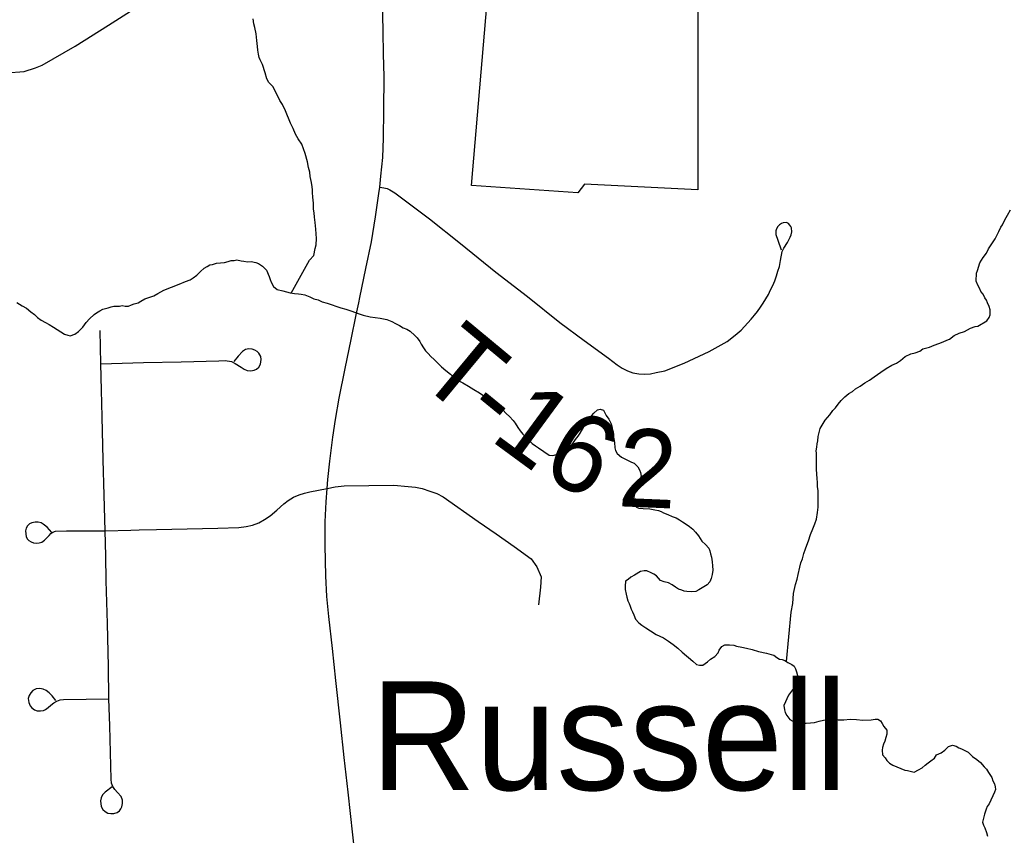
# Model space of a CAD drawing. Extents: x -11.4 to 84.1, y 11.1 to 59.
# Drawn here: x 28.225 to 28.944, y 44.128 to 44.72 of the extents above; entities that cross this region are included whole.
import ezdxf

# ---------------------------------------------------------------- set-up
doc = ezdxf.new("R2010")
doc.units = 0
for name, color, linetype in [('GM_X_Corporation', 7, 'Continuous'), ('GM_X_Minor_River', 7, 'Continuous'), ('GM_X_State_Route', 7, 'Continuous'), ('GM_X_Township_Road', 7, 'Continuous'), ('GM_X_Township_Road_Text', 7, 'Continuous'), ('GM_X_Unincorporated_Text', 7, 'Continuous')]:
    doc.layers.add(name, color=color, linetype=linetype)

msp = doc.modelspace()

# ---------------------------------------------------------------- linework, layer by layer
at = {"layer": 'GM_X_Corporation'}
msp.add_lwpolyline([(28.7167, 44.89422), (28.71711, 44.59705), (28.63473, 44.60119), (28.6298, 44.59474), (28.55271, 44.60006), (28.59239, 45.06585)], dxfattribs=at)
at = {"layer": 'GM_X_Minor_River'}
for points in [[(28.42157, 44.52201), (28.43502, 44.54588), (28.438, 44.54935), (28.43906, 44.55431), (28.43977, 44.55699), (28.44008, 44.56156), (28.43958, 44.56839), (28.43912, 44.57333), (28.43868, 44.57712), (28.43825, 44.58016), (28.43782, 44.58281), (28.43779, 44.58471), (28.43775, 44.58738), (28.43729, 44.59155), (28.43724, 44.59497), (28.43721, 44.59687), (28.43679, 44.59915), (28.43636, 44.60218), (28.43594, 44.60446), (28.43552, 44.60673), (28.43509, 44.60977), (28.43427, 44.61318), (28.43344, 44.61734), (28.43183, 44.6234), (28.42943, 44.63021), (28.42671, 44.63396), (28.42475, 44.63736), (28.42316, 44.64151), (28.4212, 44.64528), (28.41763, 44.65435), (28.41528, 44.65888), (28.41333, 44.66188), (28.41135, 44.66642), (28.40822, 44.67207), (28.40551, 44.67506), (28.40394, 44.6777), (28.40274, 44.68186), (28.40074, 44.68792), (28.39916, 44.69131), (28.39837, 44.6932), (28.39795, 44.69547), (28.39752, 44.69851), (28.39709, 44.70116), (28.39665, 44.70534), (28.39618, 44.71028), (28.39535, 44.71482), (28.39454, 44.71747), (28.3941, 44.72127)], [(28.94192, 44.57856), (28.94413, 44.58239)], [(28.78144, 44.25418), (28.78495, 44.29002), (28.78598, 44.2965), (28.78662, 44.30374), (28.78803, 44.31023), (28.78911, 44.31405), (28.78981, 44.31748), (28.79124, 44.32283), (28.79195, 44.32588), (28.79304, 44.32894), (28.79411, 44.33276), (28.79519, 44.3362), (28.79629, 44.33888), (28.79738, 44.34194), (28.79882, 44.34653), (28.80065, 44.35074), (28.80211, 44.35419), (28.80319, 44.35763), (28.80386, 44.36258), (28.80456, 44.3664), (28.80451, 44.36944), (28.80446, 44.37248), (28.8044, 44.3759), (28.80436, 44.37856), (28.80393, 44.38121), (28.80388, 44.38426), (28.80383, 44.3873), (28.80334, 44.39375), (28.80326, 44.3987), (28.8032, 44.4025), (28.80315, 44.40554), (28.80311, 44.40744), (28.80345, 44.41011), (28.80379, 44.41239), (28.80413, 44.41468), (28.80446, 44.41773), (28.80588, 44.42345), (28.80958, 44.4296), (28.81293, 44.43346), (28.81516, 44.43654), (28.81703, 44.43847), (28.81888, 44.44116), (28.82111, 44.44386), (28.82373, 44.44656), (28.82673, 44.4489), (28.82936, 44.45046), (28.83161, 44.4524), (28.83499, 44.45435), (28.83837, 44.45669), (28.84176, 44.45865), (28.84514, 44.46099), (28.85001, 44.46449), (28.85377, 44.46721), (28.8579, 44.46956), (28.8613, 44.47114), (28.8643, 44.47309), (28.86768, 44.47581), (28.87182, 44.47778), (28.87485, 44.47859), (28.87824, 44.47978), (28.8805, 44.48134), (28.88541, 44.48256), (28.8888, 44.48414), (28.8922, 44.48534), (28.89522, 44.48652), (28.89786, 44.48771), (28.89975, 44.4885), (28.90312, 44.49122), (28.90689, 44.4928), (28.91067, 44.494), (28.91293, 44.49518), (28.91519, 44.49636), (28.91859, 44.49756), (28.92048, 44.49797), (28.92687, 44.50188), (28.92873, 44.50419), (28.92946, 44.5061), (28.92939, 44.5099), (28.9286, 44.51217), (28.92741, 44.51481), (28.92662, 44.5167), (28.92545, 44.51858), (28.92427, 44.52123), (28.92272, 44.5231), (28.92193, 44.52499), (28.92036, 44.52763), (28.91917, 44.53065), (28.91946, 44.53636), (28.92018, 44.53827), (28.92198, 44.54401), (28.9242, 44.54784), (28.92681, 44.55093), (28.92827, 44.55399), (28.93049, 44.55783), (28.93309, 44.5613), (28.93456, 44.56437), (28.93566, 44.56667), (28.93713, 44.56973), (28.93823, 44.57165), (28.94008, 44.5751), (28.94192, 44.57856)], [(28.35316, 44.53503), (28.35578, 44.53774), (28.3584, 44.54006), (28.36065, 44.54124), (28.36253, 44.54241), (28.36443, 44.54282), (28.36745, 44.54363), (28.37314, 44.5441), (28.37579, 44.54491), (28.37805, 44.54571), (28.38033, 44.54574), (28.38222, 44.54616), (28.38527, 44.54545), (28.38718, 44.54509), (28.38984, 44.54476), (28.3925, 44.5448), (28.39593, 44.5441), (28.39784, 44.54337), (28.40091, 44.54152), (28.40362, 44.53852), (28.4056, 44.53399), (28.40639, 44.53172), (28.40718, 44.52983), (28.40875, 44.52682), (28.41145, 44.52458), (28.41565, 44.52351), (28.41832, 44.52279), (28.42099, 44.52208), (28.42403, 44.52175), (28.42708, 44.52142), (28.42898, 44.52107), (28.43165, 44.52073), (28.43509, 44.51927), (28.43815, 44.5178), (28.4412, 44.51709), (28.44427, 44.51561), (28.4477, 44.51453), (28.45763, 44.51127), (28.46145, 44.51019), (28.46565, 44.50874), (28.46948, 44.50728), (28.47406, 44.50584), (28.47901, 44.50478), (28.48625, 44.50376), (28.4912, 44.5027), (28.49465, 44.50123), (28.49733, 44.49976), (28.50039, 44.49829), (28.50308, 44.49681), (28.50575, 44.49571), (28.50806, 44.49423), (28.51152, 44.49124), (28.51308, 44.48937), (28.51502, 44.48674), (28.51619, 44.48485), (28.51775, 44.48222), (28.51931, 44.47996), (28.52124, 44.47809), (28.52318, 44.47584), (28.52549, 44.4736), (28.5282, 44.47098), (28.5309, 44.46837), (28.53398, 44.46576), (28.53744, 44.46315), (28.54093, 44.45941), (28.54629, 44.45683), (28.55051, 44.45424), (28.55434, 44.45202), (28.55856, 44.44943), (28.5624, 44.44683), (28.56625, 44.44423), (28.56971, 44.44163), (28.57279, 44.4394), (28.57548, 44.43716), (28.5778, 44.43453), (28.58012, 44.43229), (28.58283, 44.42929), (28.58438, 44.42742), (28.58633, 44.42441), (28.58789, 44.42177), (28.58983, 44.41952), (28.59215, 44.41728), (28.59447, 44.41503), (28.59678, 44.41279), (28.59909, 44.41093), (28.6014, 44.40945), (28.60908, 44.40425), (28.61174, 44.40391), (28.61439, 44.40471), (28.61778, 44.40629), (28.62079, 44.40786), (28.62342, 44.40981), (28.62529, 44.41136), (28.62678, 44.41328), (28.62826, 44.41559), (28.63012, 44.4179), (28.6316, 44.42021), (28.63418, 44.42481), (28.63714, 44.42981), (28.63974, 44.43289), (28.64161, 44.43482)], [(28.22246, 44.51501), (28.22629, 44.51279), (28.22936, 44.51094), (28.23245, 44.50833), (28.23514, 44.50647), (28.23745, 44.50423), (28.24014, 44.50237), (28.24321, 44.50052), (28.2459, 44.49904), (28.24897, 44.49719), (28.25703, 44.492), (28.25932, 44.49128), (28.26122, 44.49093), (28.26462, 44.49213), (28.26725, 44.49407), (28.27024, 44.49716), (28.27284, 44.50063), (28.27507, 44.50332), (28.27844, 44.50642), (28.28032, 44.50759), (28.28257, 44.50915), (28.28483, 44.51033), (28.28861, 44.51115), (28.29088, 44.51195), (28.29277, 44.51236), (28.29467, 44.51239), (28.29695, 44.51243), (28.29884, 44.51284), (28.30112, 44.5125), (28.3034, 44.51254), (28.30567, 44.51334), (28.30755, 44.51413), (28.31058, 44.51494), (28.31246, 44.51611), (28.31547, 44.51768), (28.31887, 44.51888), (28.32189, 44.52007), (28.3249, 44.52164), (28.32904, 44.52399), (28.3347, 44.52636), (28.34036, 44.52836), (28.34488, 44.53033), (28.34828, 44.53153), (28.35054, 44.53309), (28.35316, 44.53503)], [(28.64161, 44.43482), (28.64423, 44.43715), (28.64612, 44.43756), (28.64841, 44.43684), (28.65038, 44.43306), (28.65232, 44.43044), (28.65389, 44.42742), (28.65469, 44.42515), (28.65512, 44.42212), (28.65555, 44.4187), (28.65598, 44.41605), (28.6564, 44.41339), (28.65685, 44.4096), (28.65726, 44.4077), (28.65843, 44.40544), (28.66152, 44.40283), (28.66458, 44.40136), (28.6665, 44.40025), (28.6688, 44.39915), (28.67071, 44.39842), (28.67341, 44.3958), (28.67459, 44.39354), (28.67538, 44.39165), (28.6758, 44.38899), (28.67403, 44.38174), (28.67255, 44.37906), (28.67108, 44.37599), (28.67038, 44.37255), (28.67083, 44.36876), (28.67238, 44.3665), (28.67429, 44.36577), (28.67734, 44.36544), (28.68228, 44.36514), (28.68571, 44.36444), (28.68837, 44.3641), (28.69029, 44.36338), (28.6922, 44.36227), (28.69526, 44.36117), (28.69832, 44.3597), (28.70138, 44.35861), (28.70368, 44.35713), (28.70599, 44.35565), (28.70791, 44.35454), (28.71098, 44.35231), (28.71329, 44.35045), (28.71523, 44.34819), (28.71755, 44.34557), (28.7199, 44.34181), (28.7226, 44.33919), (28.72492, 44.33657), (28.72571, 44.33468), (28.72613, 44.3324), (28.72693, 44.33014), (28.72736, 44.32672), (28.72779, 44.32368), (28.72785, 44.32064), (28.72752, 44.3176), (28.72681, 44.31454), (28.72571, 44.31224), (28.72385, 44.30993), (28.71783, 44.30641), (28.71557, 44.30523), (28.71216, 44.30479), (28.70911, 44.30513), (28.70721, 44.30548), (28.7053, 44.3062), (28.70301, 44.30693), (28.7007, 44.30841), (28.6984, 44.30989), (28.69572, 44.31137), (28.69267, 44.31208), (28.68999, 44.31318), (28.6869, 44.31655), (28.68497, 44.31766), (28.68306, 44.31877), (28.67999, 44.32024), (28.6781, 44.32021), (28.67544, 44.31978), (28.67093, 44.31705), (28.6683, 44.31548), (28.66643, 44.31393), (28.66455, 44.31276), (28.66423, 44.30895), (28.66427, 44.30667), (28.66509, 44.30326), (28.6655, 44.30099), (28.66631, 44.29834), (28.6671, 44.29645), (28.66789, 44.29456), (28.66869, 44.29229), (28.66948, 44.29041), (28.67066, 44.28814), (28.67185, 44.28512), (28.67417, 44.2825), (28.67648, 44.28063), (28.67917, 44.27877), (28.68263, 44.27655), (28.68685, 44.27396), (28.69221, 44.27138), (28.69566, 44.26916), (28.69913, 44.26656)], [(28.69913, 44.26656), (28.70259, 44.26395), (28.70568, 44.26096), (28.71338, 44.25462), (28.71608, 44.25201), (28.71837, 44.25166), (28.72065, 44.2517), (28.72403, 44.25404), (28.72627, 44.25598), (28.72928, 44.25793), (28.73189, 44.26063), (28.73262, 44.26254), (28.73447, 44.26524), (28.73673, 44.26641), (28.74015, 44.26647), (28.74319, 44.26614), (28.7451, 44.26541), (28.74891, 44.26471), (28.75234, 44.26401), (28.75654, 44.26294), (28.76112, 44.26149), (28.76684, 44.26045), (28.77027, 44.25936), (28.77218, 44.25901), (28.77449, 44.25715), (28.77641, 44.25604), (28.77831, 44.25569), (28.78022, 44.25496), (28.78253, 44.25348), (28.78521, 44.252), (28.78713, 44.25089), (28.78792, 44.249), (28.78872, 44.24674), (28.78952, 44.24409), (28.79031, 44.2422), (28.78961, 44.23876), (28.78738, 44.23569), (28.7859, 44.23376), (28.78292, 44.22991), (28.77963, 44.22225), (28.78006, 44.21921), (28.78047, 44.21732), (28.78165, 44.21506), (28.78398, 44.21205), (28.7882, 44.20984), (28.79124, 44.20951), (28.7958, 44.20959), (28.79883, 44.20964), (28.80186, 44.21006), (28.80527, 44.21088), (28.80829, 44.21169), (28.81171, 44.21213), (28.81512, 44.21219), (28.81893, 44.21187), (28.82311, 44.21194), (28.82765, 44.21239), (28.83222, 44.21209), (28.83678, 44.21178), (28.84286, 44.21188), (28.84589, 44.21231), (28.84778, 44.21234), (28.8497, 44.21123), (28.85087, 44.20935), (28.85205, 44.20709), (28.85437, 44.20446), (28.85443, 44.20142), (28.8537, 44.19913), (28.85299, 44.19646), (28.85189, 44.19416), (28.85117, 44.19187), (28.85082, 44.18996), (28.85126, 44.18654), (28.85319, 44.18429), (28.85436, 44.18241), (28.85629, 44.18054), (28.8586, 44.17906), (28.8674, 44.1754), (28.8693, 44.17505), (28.87235, 44.17434), (28.87425, 44.17399), (28.87727, 44.17556), (28.8799, 44.17713), (28.88215, 44.17906), (28.8844, 44.18062), (28.88627, 44.18217), (28.8889, 44.18412), (28.89038, 44.18643), (28.89377, 44.188), (28.8964, 44.18995), (28.89901, 44.19265), (28.90204, 44.19346), (28.90471, 44.19275), (28.90662, 44.19164), (28.90854, 44.19091), (28.91045, 44.1898), (28.91352, 44.18833), (28.9166, 44.18534), (28.91968, 44.1831), (28.92238, 44.18087), (28.92509, 44.17787), (28.92664, 44.17599)], [(28.92664, 44.17599), (28.92819, 44.17374), (28.93054, 44.16998), (28.93133, 44.16771), (28.93251, 44.16544), (28.93293, 44.16317), (28.93334, 44.16127), (28.93261, 44.15936), (28.92858, 44.15093), (28.92709, 44.149), (28.92636, 44.14709), (28.92529, 44.14327), (28.92421, 44.13945), (28.92386, 44.13754), (28.92466, 44.13527), (28.92545, 44.13339), (28.92665, 44.12998), (28.92745, 44.12734)]]:
    msp.add_lwpolyline(points, dxfattribs=at)
at = {"layer": 'GM_X_State_Route'}
for points in [[(28.47159, 44.51879), (28.47595, 44.53978), (28.47988, 44.55917), (28.48301, 44.57747), (28.48529, 44.59421), (28.486, 44.599), (28.48687, 44.60693), (28.48812, 44.62044), (28.48867, 44.63458), (28.48907, 44.65477), (28.48914, 44.67919), (28.48879, 44.69557), (28.48844, 44.71194), (28.48804, 44.7359)], [(28.46972, 44.09753), (28.46635, 44.12842), (28.46299, 44.15931), (28.46025, 44.18448), (28.4575, 44.20964), (28.45413, 44.24052), (28.45158, 44.26378), (28.44904, 44.28705), (28.44753, 44.30146), (28.44686, 44.31654), (28.44645, 44.33857), (28.44628, 44.35566), (28.44711, 44.37032), (28.44775, 44.38003), (28.4482, 44.38648), (28.44963, 44.39972), (28.45197, 44.41723), (28.4538, 44.43012), (28.45662, 44.44559), (28.46079, 44.46727), (28.46519, 44.48825), (28.46896, 44.50623), (28.47076, 44.5148), (28.47159, 44.51879)]]:
    msp.add_lwpolyline(points, dxfattribs=at)
at = {"layer": 'GM_X_Township_Road'}
for points in [[(28.10863, 44.73536), (28.13583, 44.72036), (28.15601, 44.70922), (28.17619, 44.69809), (28.1974, 44.68659), (28.20379, 44.68382), (28.20885, 44.68256), (28.21476, 44.68189), (28.22782, 44.68287), (28.23605, 44.68556), (28.24088, 44.68748), (28.26486, 44.70144), (28.28895, 44.71665), (28.31305, 44.73187)], [(28.486, 44.599), (28.48907, 44.59845), (28.4915, 44.59782), (28.49323, 44.59703), (28.49684, 44.59468), (28.50948, 44.58534), (28.52213, 44.57601), (28.54459, 44.55789), (28.55747, 44.54749), (28.57036, 44.5371), (28.59321, 44.51943), (28.61686, 44.50058), (28.63457, 44.4876), (28.65227, 44.47462), (28.65853, 44.46978), (28.66204, 44.46739), (28.66587, 44.46548), (28.6699, 44.46411), (28.67412, 44.46328), (28.67838, 44.46302), (28.68264, 44.46334), (28.68681, 44.46422), (28.6931, 44.46541), (28.70713, 44.47099), (28.72525, 44.47945), (28.73823, 44.48684), (28.74408, 44.49133), (28.74849, 44.49499), (28.7533, 44.50034), (28.75576, 44.50303), (28.75814, 44.50581), (28.76041, 44.50867), (28.76254, 44.51163), (28.76458, 44.51467), (28.76653, 44.51779), (28.76828, 44.52097), (28.76994, 44.52423), (28.77146, 44.52756), (28.77288, 44.53093), (28.77411, 44.53437), (28.77526, 44.53785), (28.77625, 44.54137), (28.77707, 44.54558), (28.77834, 44.55212), (28.77943, 44.5546), (28.78216, 44.5587), (28.78423, 44.56248), (28.78487, 44.56439), (28.7853, 44.56644), (28.78502, 44.56937), (28.78454, 44.57037), (28.78398, 44.5714), (28.78287, 44.57252), (28.78149, 44.57314), (28.77905, 44.57304), (28.7777, 44.57242), (28.77628, 44.57161), (28.77527, 44.57027), (28.77417, 44.56855), (28.7737, 44.56707), (28.77379, 44.5646), (28.77506, 44.56044), (28.77761, 44.5534)], [(28.29163, 44.16313), (28.28665, 44.15928), (28.28468, 44.15732), (28.28355, 44.1552), (28.28306, 44.15302), (28.28373, 44.14887), (28.28491, 44.14688), (28.28654, 44.14526), (28.28854, 44.14419), (28.29055, 44.14378), (28.29282, 44.14392), (28.29519, 44.14447), (28.29693, 44.14575), (28.29804, 44.14726), (28.29871, 44.14874), (28.29924, 44.15101), (28.29911, 44.15355), (28.29817, 44.15622), (28.29542, 44.15913), (28.2936, 44.16124), (28.29217, 44.16359), (28.29126, 44.16585), (28.291, 44.1688), (28.29042, 44.18814), (28.28984, 44.20749), (28.28926, 44.22715), (28.28895, 44.25072), (28.28816, 44.28178), (28.28737, 44.31283), (28.28691, 44.33105), (28.28645, 44.34926), (28.28573, 44.37507), (28.28502, 44.40088), (28.28425, 44.43194), (28.28377, 44.4513), (28.28329, 44.47067), (28.28302, 44.4948)], [(28.28329, 44.47067), (28.31435, 44.47142), (28.34174, 44.47209), (28.36913, 44.47275), (28.3738, 44.47287), (28.37822, 44.47227), (28.381, 44.47091), (28.38523, 44.46809), (28.38747, 44.46675), (28.38976, 44.46573), (28.3924, 44.46548), (28.39477, 44.46599), (28.39639, 44.46667), (28.39811, 44.46809), (28.39936, 44.47023), (28.39995, 44.4738), (28.3997, 44.47592), (28.39824, 44.4782), (28.39707, 44.47949), (28.39528, 44.48051), (28.39342, 44.48111), (28.39087, 44.48144), (28.38854, 44.48103), (28.3862, 44.47949), (28.38321, 44.47614), (28.38005, 44.47215)], [(28.3113, 44.34984), (28.32372, 44.35013), (28.34601, 44.35066), (28.36831, 44.35119), (28.38361, 44.35155), (28.38906, 44.35231), (28.3935, 44.3534), (28.39828, 44.35515), (28.40238, 44.35734), (28.40648, 44.36018), (28.41126, 44.3642), (28.41628, 44.36889), (28.41955, 44.37132), (28.4234, 44.37367), (28.42734, 44.37543), (28.43145, 44.3766), (28.43514, 44.37744), (28.44775, 44.38003)], [(28.44775, 44.38003), (28.45367, 44.38126), (28.4601, 44.38188), (28.47815, 44.38213), (28.4962, 44.38238), (28.50659, 44.38154), (28.51187, 44.38095), (28.51673, 44.37995), (28.52243, 44.37811), (28.52743, 44.3764), (28.53198, 44.37388), (28.55747, 44.35612), (28.57061, 44.34696), (28.58374, 44.33781), (28.59589, 44.32885), (28.60008, 44.32315), (28.60318, 44.31578), (28.60276, 44.30833), (28.60131, 44.29553)], [(28.24772, 44.34805), (28.24448, 44.35189), (28.2416, 44.35401), (28.24007, 44.35503), (28.23778, 44.35554), (28.23565, 44.35563), (28.23337, 44.35508), (28.2316, 44.3542), (28.23016, 44.35287), (28.22921, 44.35109), (28.22866, 44.34932), (28.2292, 44.34475), (28.23005, 44.34314), (28.23107, 44.34212), (28.23271, 44.34112), (28.23459, 44.34056), (28.23681, 44.34023), (28.23863, 44.3404), (28.24052, 44.34101), (28.24253, 44.34238), (28.24576, 44.34595), (28.24712, 44.34732), (28.24848, 44.34824), (28.25038, 44.34895), (28.25838, 44.34912), (28.28645, 44.34926), (28.30509, 44.34969), (28.3113, 44.34984)], [(28.25066, 44.22596), (28.24807, 44.22944), (28.2459, 44.23163), (28.24361, 44.23328), (28.24157, 44.23419), (28.23917, 44.2346), (28.23643, 44.23434), (28.23409, 44.2332), (28.23243, 44.23154), (28.23122, 44.22965), (28.23061, 44.22744), (28.23102, 44.22452), (28.23202, 44.22211), (28.23332, 44.22057), (28.23513, 44.21927), (28.23706, 44.21848), (28.23967, 44.21836), (28.2417, 44.21876), (28.24311, 44.21948), (28.24512, 44.2208), (28.24701, 44.22255), (28.24917, 44.22417), (28.25151, 44.22556), (28.25393, 44.22644), (28.25627, 44.22674), (28.27277, 44.22695), (28.28926, 44.22715)]]:
    msp.add_lwpolyline(points, dxfattribs=at)

# ---------------------------------------------------------------- texts
at = {"layer": 'GM_X_Township_Road_Text'}
for s, rotation, p in [('T', 320.32283, (28.51136, 44.46003)), ('-', 320.76868, (28.54444, 44.43258)), ('1', 323.74153, (28.56506, 44.41586)), ('6', 332.61507, (28.60143, 44.39011)), ('2', 357.58777, (28.65839, 44.36712))]:
    msp.add_text(s, height=0.05682, rotation=rotation, dxfattribs=at).set_placement(p)
at = {"layer": 'GM_X_Unincorporated_Text'}
msp.add_text('Russell', height=0.078977, rotation=0.00001, dxfattribs=at).set_placement((28.47937, 44.16085))

doc.saveas('drawing.dxf')
